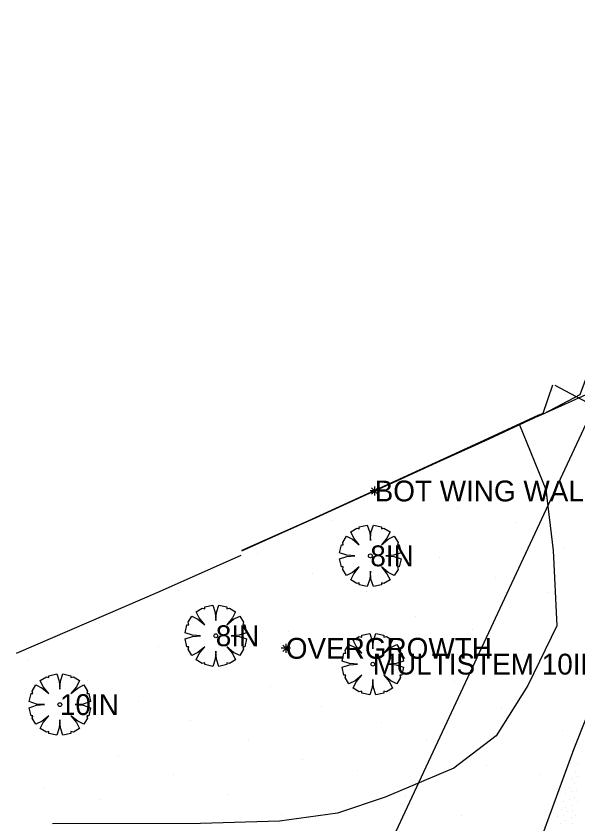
# Model space of a CAD drawing. Extents: x 1729983 to 1730242, y 468641 to 469019.
# Drawn here: x 1729983.3 to 1730031.8, y 468742.1 to 468811.9 of the extents above; entities that cross this region are included whole.
import ezdxf

# ---------------------------------------------------------------- set-up
doc = ezdxf.new("R2010")
doc.units = 0
for name, color, linetype in [('Default', 7, 'Continuous'), ('S_Bridge_Abutment_Bottom', 7, 'Continuous'), ('S_Bridge_Wingwall', 7, 'Continuous'), ('S_Fencing_ChainLink', 7, 'Continuous'), ('S_Ground_SpotElevation', 7, 'Continuous'), ('S_Misc_MiscFeature', 7, 'Continuous'), ('S_Misc_MiscItems', 7, 'Continuous'), ('S_Roadway_Sidewalks', 7, 'Continuous'), ('S_Text', 7, 'Continuous'), ('S_Trees_Bush_Line', 7, 'Continuous'), ('S_Trees_Decid_NonPay', 7, 'Continuous'), ('S_Utilities_AG_Communications', 7, 'Continuous')]:
    doc.layers.add(name, color=color, linetype=linetype)

# ---------------------------------------------------------------- blocks, each defined once
blk = doc.blocks.new('POINT_DISPLAY')
at = {"layer": 'Default'}
blk.add_line((0, 0), (0, 0), dxfattribs=at)

msp = doc.modelspace()

# ---------------------------------------------------------------- linework, layer by layer
at = {"layer": 'S_Bridge_Abutment_Bottom'}
msp.add_lwpolyline([(1730028.397, 468777.334), (1730030.386, 468778.233), (1730033.055, 468779.454), (1730033.218, 468779.896), (1730038.37, 468793.886), (1730045.609, 468813.805), (1730053.552, 468835.326), (1730061.264, 468856.585), (1730068.104, 468874.933), (1730077.288, 468899.639), (1730081.24, 468910.357), (1730081.674, 468911.604), (1730082.174, 468913.008), (1730079.112, 468916.385)], dxfattribs=at)
at = {"layer": 'S_Bridge_Wingwall'}
msp.add_lwpolyline([(1730028.364, 468777.408), (1730022.915, 468774.887), (1730008.801, 468768.401), (1730002.791, 468765.724)], dxfattribs=at)
at = {"layer": 'S_Fencing_ChainLink'}
msp.add_lwpolyline([(1730002.681, 468765.277), (1729995.646, 468762.145), (1729983.304, 468756.814)], dxfattribs=at)
at = {"layer": 'S_Misc_MiscFeature'}
msp.add_line((1730029.794, 468780.002), (1730056.391, 468765.781), dxfattribs=at)
for points in [[(1730028.819, 468777.529), (1730031.975, 468779.199), (1730034.887, 468787.021), (1730045.144, 468814.963), (1730055.236, 468842.487), (1730058.712, 468851.879), (1730068.635, 468878.922), (1730072.147, 468888.181), (1730075.727, 468897.903), (1730078.619, 468905.503), (1730081.717, 468913.484), (1730079.668, 468915.827)], [(1730028.364, 468777.408), (1730028.769, 468777.584), (1730029.623, 468780.036)], [(1730028.397, 468777.334), (1730026.742, 468776.568), (1730024.083, 468775.343), (1730019.575, 468773.303), (1730015.808, 468771.554), (1730013.438, 468770.504), (1730009.164, 468768.533), (1730005.944, 468767.114), (1730002.745, 468765.676)]]:
    msp.add_lwpolyline(points, dxfattribs=at)
at = {"layer": 'S_Misc_MiscItems'}
for p, q in [((1730014.502, 468770.597), (1730013.978, 468771.121)), ((1730014.502, 468771.121), (1730013.978, 468770.597)), ((1730014.24, 468771.252), (1730014.24, 468770.466)), ((1730014.633, 468770.859), (1730013.847, 468770.859)), ((1730006.571, 468757.666), (1730006.571, 468756.88)), ((1730006.964, 468757.273), (1730006.178, 468757.273)), ((1730006.833, 468757.011), (1730006.309, 468757.535)), ((1730006.833, 468757.535), (1730006.309, 468757.011))]:
    msp.add_line(p, q, dxfattribs=at)
at = {"layer": 'S_Roadway_Sidewalks'}
msp.add_lwpolyline([(1730033.218, 468779.896), (1730040.852, 468776.278), (1730041.205, 468774.325), (1730039.473, 468769.232), (1730035.785, 468759.578), (1730031.436, 468748.602), (1730024.922, 468730.8), (1730019.096, 468714.972), (1730012.838, 468697.998)], dxfattribs=at)
at = {"layer": 'S_Trees_Bush_Line'}
msp.add_lwpolyline([(1730026.742, 468776.568), (1730029.011, 468770.977), (1730029.636, 468765.723), (1730029.97, 468759.217), (1730027.451, 468754.063), (1730024.715, 468749.707), (1730021.08, 468746.918), (1730015.137, 468744.413), (1730011.035, 468743.038), (1730006.035, 468742.36), (1729999.209, 468742.138), (1729986.428, 468742.121)], dxfattribs=at)
at = {"layer": 'S_Trees_Decid_NonPay'}
for points in [[(1730012.541, 468765.257), (1730011.852, 468765.31), (1730011.215, 468765.522), (1730011.374, 468766.212), (1730011.533, 468766.212), (1730011.48, 468766.424), (1730011.798, 468766.954), (1730012.328, 468766.689), (1730012.913, 468766.212), (1730012.435, 468766.795), (1730012.17, 468767.326), (1730012.7, 468767.644), (1730012.913, 468767.591), (1730012.913, 468767.75), (1730013.602, 468767.909), (1730013.814, 468767.273), (1730013.867, 468766.583), (1730013.92, 468767.273), (1730014.132, 468767.909), (1730014.822, 468767.75), (1730014.822, 468767.591), (1730015.034, 468767.644), (1730015.565, 468767.326), (1730015.299, 468766.795), (1730014.822, 468766.212), (1730015.405, 468766.689), (1730015.935, 468766.954), (1730016.254, 468766.424), (1730016.201, 468766.212), (1730016.36, 468766.212), (1730016.52, 468765.522), (1730015.883, 468765.31), (1730015.193, 468765.257), (1730015.883, 468765.204), (1730016.52, 468764.992), (1730016.36, 468764.302), (1730016.201, 468764.302), (1730016.254, 468764.09), (1730015.935, 468763.56), (1730015.405, 468763.825), (1730014.822, 468764.302), (1730015.299, 468763.719), (1730015.565, 468763.188), (1730015.034, 468762.87), (1730014.822, 468762.923), (1730014.822, 468762.764), (1730014.132, 468762.605), (1730013.92, 468763.241), (1730013.867, 468763.931), (1730013.814, 468763.241), (1730013.602, 468762.605), (1730012.913, 468762.764), (1730012.913, 468762.923), (1730012.7, 468762.87), (1730012.17, 468763.188), (1730012.435, 468763.719), (1730012.913, 468764.302), (1730012.328, 468763.825), (1730011.798, 468763.56), (1730011.48, 468764.09), (1730011.533, 468764.302), (1730011.374, 468764.302), (1730011.215, 468764.992), (1730011.852, 468765.204), (1730012.541, 468765.257)], [(1729999.206, 468758.357), (1729998.517, 468758.41), (1729997.88, 468758.622), (1729998.039, 468759.312), (1729998.198, 468759.312), (1729998.145, 468759.524), (1729998.463, 468760.054), (1729998.993, 468759.789), (1729999.578, 468759.312), (1729999.1, 468759.895), (1729998.835, 468760.426), (1729999.365, 468760.744), (1729999.578, 468760.691), (1729999.578, 468760.85), (1730000.267, 468761.009), (1730000.479, 468760.373), (1730000.532, 468759.683), (1730000.585, 468760.373), (1730000.797, 468761.009), (1730001.487, 468760.85), (1730001.487, 468760.691), (1730001.699, 468760.744), (1730002.23, 468760.426), (1730001.964, 468759.895), (1730001.487, 468759.312), (1730002.07, 468759.789), (1730002.6, 468760.054), (1730002.919, 468759.524), (1730002.866, 468759.312), (1730003.025, 468759.312), (1730003.185, 468758.622), (1730002.548, 468758.41), (1730001.858, 468758.357), (1730002.548, 468758.304), (1730003.185, 468758.092), (1730003.025, 468757.402), (1730002.866, 468757.402), (1730002.919, 468757.19), (1730002.6, 468756.66), (1730002.07, 468756.925), (1730001.487, 468757.402), (1730001.964, 468756.819), (1730002.23, 468756.288), (1730001.699, 468755.97), (1730001.487, 468756.023), (1730001.487, 468755.864), (1730000.797, 468755.705), (1730000.585, 468756.341), (1730000.532, 468757.031), (1730000.479, 468756.341), (1730000.267, 468755.705), (1729999.578, 468755.864), (1729999.578, 468756.023), (1729999.365, 468755.97), (1729998.835, 468756.288), (1729999.1, 468756.819), (1729999.578, 468757.402), (1729998.993, 468756.925), (1729998.463, 468756.66), (1729998.145, 468757.19), (1729998.198, 468757.402), (1729998.039, 468757.402), (1729997.88, 468758.092), (1729998.517, 468758.304), (1729999.206, 468758.357)], [(1730012.757, 468755.907), (1730012.068, 468755.96), (1730011.431, 468756.172), (1730011.59, 468756.862), (1730011.749, 468756.862), (1730011.696, 468757.074), (1730012.014, 468757.604), (1730012.544, 468757.339), (1730013.129, 468756.862), (1730012.651, 468757.445), (1730012.386, 468757.976), (1730012.916, 468758.294), (1730013.129, 468758.241), (1730013.129, 468758.4), (1730013.818, 468758.559), (1730014.03, 468757.923), (1730014.083, 468757.233), (1730014.136, 468757.923), (1730014.348, 468758.559), (1730015.038, 468758.4), (1730015.038, 468758.241), (1730015.25, 468758.294), (1730015.781, 468757.976), (1730015.515, 468757.445), (1730015.038, 468756.862), (1730015.621, 468757.339), (1730016.151, 468757.604), (1730016.47, 468757.074), (1730016.417, 468756.862), (1730016.576, 468756.862), (1730016.736, 468756.172), (1730016.099, 468755.96), (1730015.409, 468755.907), (1730016.099, 468755.854), (1730016.736, 468755.642), (1730016.576, 468754.952), (1730016.417, 468754.952), (1730016.47, 468754.74), (1730016.151, 468754.21), (1730015.621, 468754.475), (1730015.038, 468754.952), (1730015.515, 468754.369), (1730015.781, 468753.838), (1730015.25, 468753.52), (1730015.038, 468753.573), (1730015.038, 468753.414), (1730014.348, 468753.255), (1730014.136, 468753.891), (1730014.083, 468754.581), (1730014.03, 468753.891), (1730013.818, 468753.255), (1730013.129, 468753.414), (1730013.129, 468753.573), (1730012.916, 468753.52), (1730012.386, 468753.838), (1730012.651, 468754.369), (1730013.129, 468754.952), (1730012.544, 468754.475), (1730012.014, 468754.21), (1730011.696, 468754.74), (1730011.749, 468754.952), (1730011.59, 468754.952), (1730011.431, 468755.642), (1730012.068, 468755.854), (1730012.757, 468755.907)], [(1729985.751, 468752.412), (1729985.062, 468752.465), (1729984.425, 468752.677), (1729984.584, 468753.367), (1729984.743, 468753.367), (1729984.69, 468753.579), (1729985.008, 468754.109), (1729985.538, 468753.844), (1729986.123, 468753.367), (1729985.645, 468753.95), (1729985.38, 468754.481), (1729985.91, 468754.799), (1729986.123, 468754.746), (1729986.123, 468754.905), (1729986.812, 468755.064), (1729987.024, 468754.428), (1729987.077, 468753.738), (1729987.13, 468754.428), (1729987.342, 468755.064), (1729988.032, 468754.905), (1729988.032, 468754.746), (1729988.244, 468754.799), (1729988.775, 468754.481), (1729988.509, 468753.95), (1729988.032, 468753.367), (1729988.615, 468753.844), (1729989.145, 468754.109), (1729989.464, 468753.579), (1729989.411, 468753.367), (1729989.57, 468753.367), (1729989.73, 468752.677), (1729989.093, 468752.465), (1729988.403, 468752.412), (1729989.093, 468752.359), (1729989.73, 468752.147), (1729989.57, 468751.457), (1729989.411, 468751.457), (1729989.464, 468751.245), (1729989.145, 468750.715), (1729988.615, 468750.98), (1729988.032, 468751.457), (1729988.509, 468750.874), (1729988.775, 468750.343), (1729988.244, 468750.025), (1729988.032, 468750.078), (1729988.032, 468749.919), (1729987.342, 468749.76), (1729987.13, 468750.396), (1729987.077, 468751.086), (1729987.024, 468750.396), (1729986.812, 468749.76), (1729986.123, 468749.919), (1729986.123, 468750.078), (1729985.91, 468750.025), (1729985.38, 468750.343), (1729985.645, 468750.874), (1729986.123, 468751.457), (1729985.538, 468750.98), (1729985.008, 468750.715), (1729984.69, 468751.245), (1729984.743, 468751.457), (1729984.584, 468751.457), (1729984.425, 468752.147), (1729985.062, 468752.359), (1729985.751, 468752.412)]]:
    msp.add_lwpolyline(points, dxfattribs=at)
for centre in [(1730013.867, 468765.257), (1730000.532, 468758.357), (1730014.083, 468755.907), (1729987.077, 468752.412)]:
    msp.add_circle(centre, 0.166, dxfattribs=at)
at = {"layer": 'S_Utilities_AG_Communications'}
msp.add_lwpolyline([(1730120.945, 469004.632), (1730097.184, 468954.408), (1730085.556, 468926.546), (1730082.304, 468910.964), (1730034.658, 468781.323), (1729998.254, 468703.261)], dxfattribs=at)

# ---------------------------------------------------------------- block references
at = {"layer": 'S_Ground_SpotElevation'}
for p in [(1730027.81, 468772.372), (1730021.417, 468769.418), (1730010.492, 468768.295), (1730026.419, 468768.173), (1730015.23, 468766.914), (1730004.131, 468765.481), (1730030.653, 468765.891), (1730019.874, 468765.098), (1730008.862, 468763.712), (1730024.705, 468763.379), (1729997.271, 468762.242), (1730013.542, 468762.153), (1730029.113, 468762.073), (1730002.097, 468760.363), (1730017.741, 468760.028), (1729990.534, 468759.397), (1730006.77, 468758.712), (1730022.665, 468758.89), (1729995.614, 468757.404), (1730011.421, 468756.944), (1729984.263, 468756.343), (1730027.164, 468756.744), (1730000.012, 468755.741), (1730016.226, 468755.217), (1729989.468, 468754.46), (1730021.097, 468754.366), (1730005.211, 468753.952), (1729993.832, 468752.689), (1730009.682, 468752.228), (1730025.218, 468752.062), (1729998.337, 468751.04), (1730014.845, 468750.858), (1730030.456, 468750.141), (1729987.641, 468749.787), (1730003.395, 468749.32), (1730018.718, 468749.273), (1729992.115, 468747.937), (1730008, 468747.634), (1730031.707, 468747.338), (1730012.72, 468746.737), (1730023.878, 468747.113), (1730031.53, 468746.591), (1729996.867, 468746.352), (1730028.467, 468746.341), (1730031.259, 468746.01), (1730031.711, 468746.18), (1729985.703, 468745.221), (1730031.053, 468745.278), (1730031.458, 468745.582), (1730001.626, 468744.667), (1730016.936, 468744.561), (1730030.74, 468744.729), (1730031.189, 468744.884), (1730031.46, 468744.426), (1730031.699, 468745.025), (1729990.561, 468744.195), (1730030.533, 468744.016), (1730031.024, 468744.182), (1730031.199, 468743.697), (1730031.731, 468744.01), (1730030.321, 468743.314), (1730030.718, 468743.558), (1730030.913, 468743.16), (1730031.34, 468743.298), (1730006.18, 468742.959), (1730021.744, 468742.855), (1730030.059, 468742.742), (1730030.547, 468742.827), (1730030.727, 468742.392), (1730031.234, 468742.644), (1730031.574, 468742.841), (1730030.306, 468742.186), (1730031.336, 468742.129)]:
    msp.add_blockref('POINT_DISPLAY', p, dxfattribs=at)

# ---------------------------------------------------------------- texts
at = {"layer": 'S_Text'}
for s, p in [('BOT WING WALL', (1730014.24, 468769.959)), ('8IN', (1730013.867, 468764.357)), ('8IN', (1730000.532, 468757.457)), ('OVERGROWTH', (1730006.571, 468756.373)), ('MULTISTEM 10IN 8IN', (1730014.083, 468755.007)), ('10IN', (1729987.077, 468751.512))]:
    msp.add_text(s, height=1.8, dxfattribs=at).set_placement(p)

doc.saveas('drawing.dxf')
